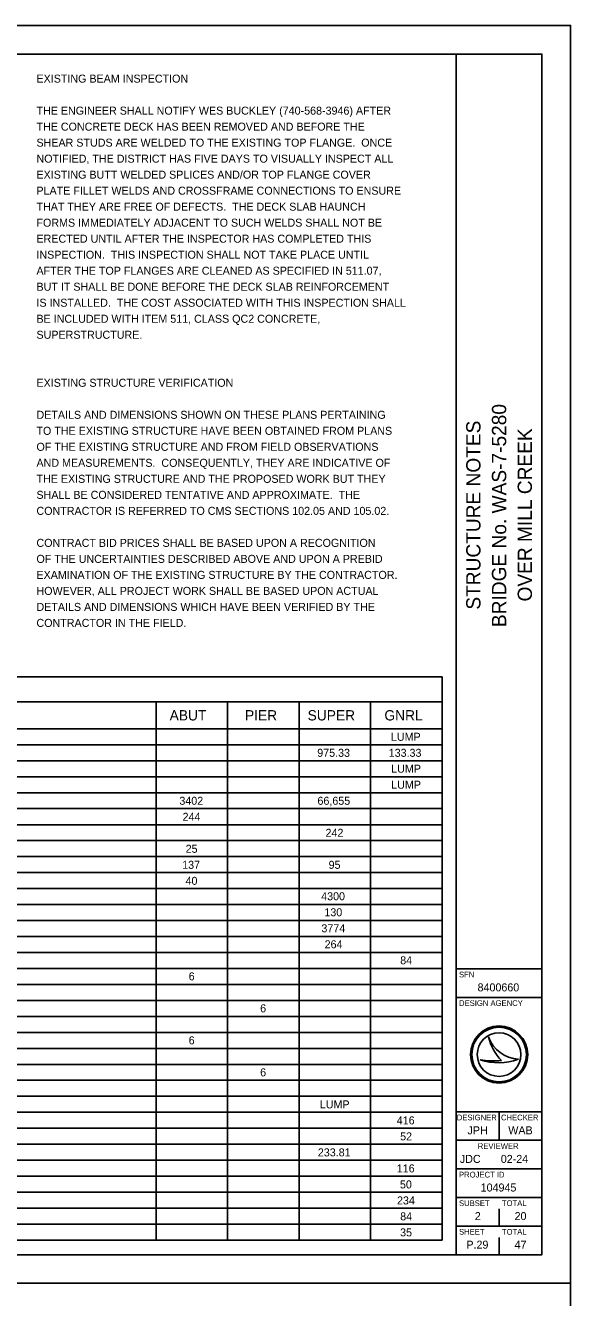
# Model space of a CAD drawing. Extents: x -7.7 to 67.3, y -22 to 22.
# Drawn here: x 24.47 to 34, y -0.25 to 22 of the extents above; entities that cross this region are included whole.
import ezdxf

# ---------------------------------------------------------------- set-up
doc = ezdxf.new("R2010")
doc.units = 0
for name, color, linetype in [('BR_P_Gen_Text', 7, 'Continuous'), ('SH_Border', 7, 'Continuous'), ('SH_Cut_Line', 7, 'Continuous'), ('SH_Data', 7, 'Continuous'), ('SH_Text', 7, 'Continuous'), ('TX_P_1', 7, 'Continuous')]:
    doc.layers.add(name, color=color, linetype=linetype)

msp = doc.modelspace()

# ---------------------------------------------------------------- linework, layer by layer
at = {"layer": 'BR_P_Gen_Text'}
for p, q in [((31.753, 10.606), (31.753, 0.755)), ((26.753, 10.171), (26.753, 0.755)), ((28.003, 10.171), (28.003, 0.755)), ((29.253, 10.171), (29.253, 0.755)), ((30.503, 10.171), (30.503, 0.755)), ((10.494, 9.698), (31.753, 9.698)), ((10.494, 9.418), (31.753, 9.418)), ((10.494, 9.139), (31.753, 9.139)), ((10.494, 8.86), (31.753, 8.86)), ((10.494, 8.58), (31.753, 8.58)), ((10.494, 8.301), (31.753, 8.301)), ((10.494, 8.021), (31.753, 8.021)), ((10.494, 7.742), (31.753, 7.742)), ((10.494, 7.462), (31.753, 7.462)), ((10.494, 7.183), (31.753, 7.183)), ((10.494, 6.903), (31.753, 6.903)), ((10.494, 6.624), (31.753, 6.624)), ((10.494, 6.345), (31.753, 6.345)), ((10.494, 6.065), (31.753, 6.065)), ((10.494, 5.786), (31.753, 5.786)), ((10.494, 5.506), (31.753, 5.506)), ((10.494, 5.227), (31.753, 5.227)), ((10.494, 4.947), (31.753, 4.947)), ((10.494, 4.668), (31.753, 4.668)), ((10.494, 4.388), (31.753, 4.388)), ((10.494, 4.109), (31.753, 4.109)), ((10.494, 3.829), (31.753, 3.829)), ((10.494, 3.55), (31.753, 3.55)), ((10.494, 3.27), (31.753, 3.27)), ((10.494, 2.991), (31.753, 2.991)), ((10.494, 2.712), (31.753, 2.712)), ((10.494, 2.432), (31.753, 2.432)), ((10.494, 2.153), (31.753, 2.153)), ((10.494, 1.873), (31.753, 1.873)), ((10.494, 1.594), (31.753, 1.594)), ((10.494, 1.314), (31.753, 1.314)), ((10.494, 1.035), (31.753, 1.035)), ((10.494, 0.755), (31.753, 0.755))]:
    msp.add_line(p, q, dxfattribs=at)
for points in [[(31.753, 10.606), (10.494, 10.606)], [(31.753, 10.171), (10.494, 10.171)]]:
    msp.add_lwpolyline(points, dxfattribs=at)
at = {"layer": 'SH_Border'}
for p, q in [((32, 0.5), (32, 21.5)), ((32, 5.5), (33.5, 5.5)), ((32, 5), (33.5, 5)), ((32, 3), (33.5, 3)), ((32.75, 3), (32.75, 2.5)), ((32, 2.5), (33.5, 2.5)), ((32, 2), (33.5, 2)), ((32, 1.5), (33.5, 1.5)), ((32, 1), (33.5, 1))]:
    msp.add_line(p, q, dxfattribs=at)
msp.add_lwpolyline([(1.5, 21.5), (33.5, 21.5), (33.5, 0.5), (1.5, 0.5)], close=True, dxfattribs=at)
at = {"layer": 'SH_Cut_Line'}
for points in [[(0, 0), (34, 0), (34, 22), (0, 22)], [(0, -22), (34, -22), (34, 0), (0, 0)]]:
    msp.add_lwpolyline(points, close=True, dxfattribs=at)
at = {"layer": 'SH_Data'}
for p, q in [((32.567, 4.31), (32.567, 4.31)), ((32.417, 3.91), (32.417, 3.91)), ((32.75, 4), (32.75, 4)), ((33.087, 3.919), (33.087, 3.919)), ((32.75, 1), (32.75, 1.3)), ((32.375, 0.675), (32.375, 0.675)), ((32.75, 0.5), (32.75, 0.8))]:
    msp.add_line(p, q, dxfattribs=at)
for radius in [0.5, 0.477, 0.477, 0.382]:
    msp.add_circle((32.75, 4), radius, dxfattribs=at)
for centre, radius, start, end in [((33.116, 4.498), 0.58, 198.9257, 198.9319), ((33.347, 4.47), 0.796, 191.6379, 191.6421), ((33.116, 4.498), 0.58, 198.9319, 267.1657), ((33.347, 4.47), 0.796, 191.6421, 226.0947), ((32.739, 4.87), 1.013, 251.4576, 290.0832), ((32.648, 5.154), 1.266, 259.4964, 259.4995), ((32.739, 4.87), 1.013, 251.4527, 251.4576), ((32.648, 5.154), 1.266, 259.4995, 276.6672)]:
    msp.add_arc(centre, radius, start, end, dxfattribs=at)

# ---------------------------------------------------------------- texts
at = {"layer": 'BR_P_Gen_Text'}
for s, p in [('LUMP', (30.859, 9.488)), ('975.33', (29.57, 9.208)), ('133.33', (30.82, 9.208)), ('LUMP', (30.864, 8.93)), ('LUMP', (30.864, 8.65)), ('3402', (27.159, 8.369)), ('66,655', (29.574, 8.369)), ('244', (27.215, 8.089)), ('242', (29.715, 7.809)), ('25', (27.269, 7.529)), ('137', (27.208, 7.249)), ('95', (29.769, 7.249)), ('40', (27.267, 6.969)), ('4300', (29.639, 6.699)), ('130', (29.695, 6.419)), ('3774', (29.643, 6.139)), ('264', (29.699, 5.859)), ('84', (31.021, 5.579)), ('6', (27.322, 5.299)), ('6', (28.572, 4.739)), ('6', (27.322, 4.179)), ('6', (28.572, 3.619)), ('LUMP', (29.615, 3.059)), ('416', (30.961, 2.779)), ('52', (31.02, 2.499)), ('233.81', (29.581, 2.219)), ('116', (30.961, 1.939)), ('50', (31.017, 1.659)), ('234', (30.965, 1.379)), ('84', (31.021, 1.1)), ('35', (31.019, 0.82))]:
    msp.add_text(s, height=0.14, dxfattribs=at).set_placement(p)
at = {"layer": 'SH_Data'}
for s, p in [('BRIDGE No. WAS-7-5280', (32.875, 11.477)), ('STRUCTURE NOTES', (32.425, 11.782)), ('OVER MILL CREEK', (33.325, 11.925))]:
    msp.add_text(s, height=0.25, rotation=90, dxfattribs=at).set_placement(p)
for s, height, p in [('SFN', 0.1, (32.05, 5.35)), ('8400660', 0.14, (32.374, 5.105)), ('DESIGN AGENCY', 0.1, (32.05, 4.85)), ('DESIGNER', 0.1, (32.011, 2.85)), ('CHECKER', 0.1, (32.784, 2.85)), ('JPH', 0.14, (32.198, 2.605)), ('WAB', 0.14, (32.911, 2.605)), ('REVIEWER', 0.1, (32.378, 2.35)), ('JDC', 0.14, (32.064, 2.105)), ('02-24', 0.14, (32.78, 2.105)), ('PROJECT ID', 0.1, (32.05, 1.85)), ('104945', 0.14, (32.428, 1.605)), ('SUBSET', 0.1, (32.05, 1.35)), ('TOTAL', 0.1, (32.8, 1.35)), ('2', 0.14, (32.326, 1.105)), ('20', 0.14, (33.021, 1.105)), ('SHEET', 0.1, (32.05, 0.85)), ('TOTAL', 0.1, (32.8, 0.85)), ('P.29', 0.14, (32.178, 0.605)), ('47', 0.14, (33.021, 0.605))]:
    msp.add_text(s, height=height, dxfattribs=at).set_placement(p)
at = {"layer": 'SH_Text'}
for s, p in [('EXISTING BEAM INSPECTION', (24.66, 21)), ('THE ENGINEER SHALL NOTIFY WES BUCKLEY (740-568-3946) AFTER', (24.66, 20.44)), ('THE CONCRETE DECK HAS BEEN REMOVED AND BEFORE THE', (24.66, 20.16)), ('SHEAR STUDS ARE WELDED TO THE EXISTING TOP FLANGE.  ONCE', (24.66, 19.88)), ('NOTIFIED, THE DISTRICT HAS FIVE DAYS TO VISUALLY INSPECT ALL', (24.66, 19.6)), ('EXISTING BUTT WELDED SPLICES AND/OR TOP FLANGE COVER', (24.66, 19.32)), ('PLATE FILLET WELDS AND CROSSFRAME CONNECTIONS TO ENSURE', (24.66, 19.04)), ('THAT THEY ARE FREE OF DEFECTS.  THE DECK SLAB HAUNCH', (24.66, 18.76)), ('FORMS IMMEDIATELY ADJACENT TO SUCH WELDS SHALL NOT BE', (24.66, 18.48)), ('ERECTED UNTIL AFTER THE INSPECTOR HAS COMPLETED THIS', (24.66, 18.2)), ('INSPECTION.  THIS INSPECTION SHALL NOT TAKE PLACE UNTIL', (24.66, 17.92)), ('AFTER THE TOP FLANGES ARE CLEANED AS SPECIFIED IN 511.07,', (24.66, 17.64)), ('BUT IT SHALL BE DONE BEFORE THE DECK SLAB REINFORCEMENT', (24.66, 17.36)), ('IS INSTALLED.  THE COST ASSOCIATED WITH THIS INSPECTION SHALL', (24.66, 17.08)), ('BE INCLUDED WITH ITEM 511, CLASS QC2 CONCRETE,', (24.66, 16.8)), ('SUPERSTRUCTURE.', (24.66, 16.52)), ('EXISTING STRUCTURE VERIFICATION', (24.66, 15.68)), ('DETAILS AND DIMENSIONS SHOWN ON THESE PLANS PERTAINING', (24.66, 15.12)), ('TO THE EXISTING STRUCTURE HAVE BEEN OBTAINED FROM PLANS', (24.66, 14.84)), ('OF THE EXISTING STRUCTURE AND FROM FIELD OBSERVATIONS', (24.66, 14.56)), ('AND MEASUREMENTS.  CONSEQUENTLY, THEY ARE INDICATIVE OF', (24.66, 14.28)), ('THE EXISTING STRUCTURE AND THE PROPOSED WORK BUT THEY', (24.66, 14)), ('SHALL BE CONSIDERED TENTATIVE AND APPROXIMATE.  THE', (24.66, 13.72)), ('CONTRACTOR IS REFERRED TO CMS SECTIONS 102.05 AND 105.02.', (24.66, 13.44)), ('CONTRACT BID PRICES SHALL BE BASED UPON A RECOGNITION', (24.66, 12.88)), ('OF THE UNCERTAINTIES DESCRIBED ABOVE AND UPON A PREBID', (24.66, 12.6)), ('EXAMINATION OF THE EXISTING STRUCTURE BY THE CONTRACTOR.', (24.66, 12.32)), ('HOWEVER, ALL PROJECT WORK SHALL BE BASED UPON ACTUAL', (24.66, 12.04)), ('DETAILS AND DIMENSIONS WHICH HAVE BEEN VERIFIED BY THE', (24.66, 11.76)), ('CONTRACTOR IN THE FIELD.', (24.66, 11.48))]:
    msp.add_text(s, height=0.14, dxfattribs=at).set_placement(p)
at = {"layer": 'TX_P_1'}
for s, p in [('ABUT', (26.989, 9.844)), ('PIER', (28.307, 9.844)), ('SUPER', (29.402, 9.844)), ('GNRL', (30.745, 9.844))]:
    msp.add_text(s, height=0.18, dxfattribs=at).set_placement(p)

doc.saveas('drawing.dxf')
